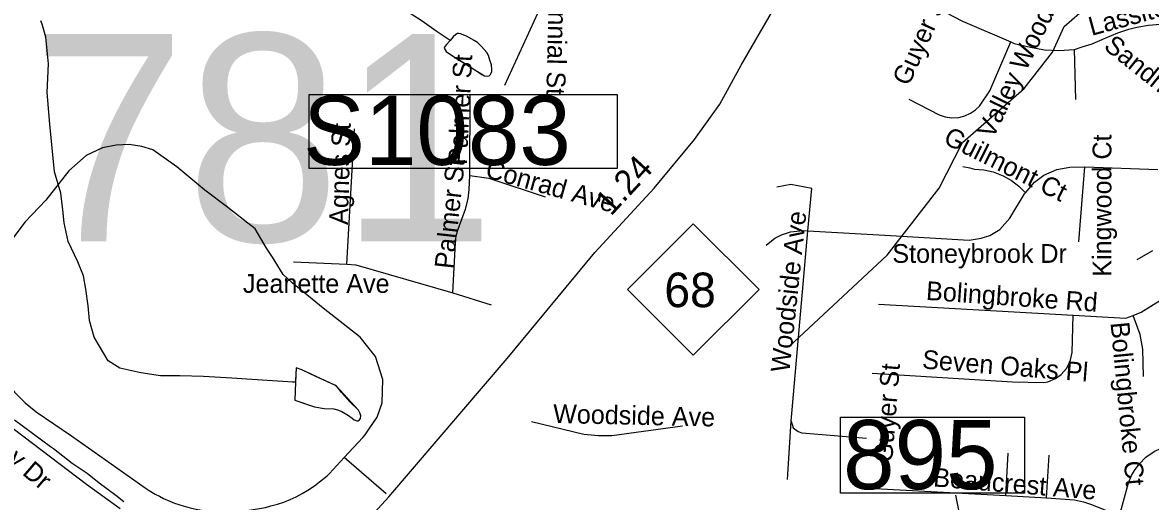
# Model space of a CAD drawing. Extents: x 1662474 to 1856135, y 779280 to 917889.
# Drawn here: x 1701527 to 1707230, y 816221 to 818646 of the extents above; entities that cross this region are included whole.
import ezdxf

# ---------------------------------------------------------------- set-up
doc = ezdxf.new("R2010")
doc.units = 0
for name, color, linetype in [('Exist Hydrographic Misc Water Feature', 7, 'Continuous'), ('Exist Hydrographic River Shore Label', 7, 'Continuous'), ('Exist Road Non-System Structure Non-Sys Other Number Label', 7, 'Continuous'), ('Exist Road Non-System Type 51', 7, 'Continuous'), ('Exist Road Non-System Type 51 Label', 7, 'Continuous'), ('Exist Road Primary NC Service Mileage Hundredths English Label', 7, 'Continuous'), ('Exist Road Primary NC Shield CELL', 7, 'Continuous'), ('Exist Road Primary NC Shield Number Label', 7, 'Continuous'), ('Exist Road Primary NC UnDivided 4 Lane Attributed', 7, 'Continuous'), ('Exist Road Secondary Structure Standard Bridge Number Label', 7, 'Continuous'), ('Exist Road Secondary Type 51 Divided Attributed', 7, 'Continuous'), ('Exist Road Secondary Type 51 Label', 7, 'Continuous')]:
    doc.layers.add(name, color=color, linetype=linetype)

msp = doc.modelspace()

# ---------------------------------------------------------------- linework, layer by layer
at = {"layer": 'Exist Hydrographic Misc Water Feature'}
for points in [[(1705403.1, 817006.2), (1705899.1, 817468.7), (1706161.1, 817808), (1706280.1, 818038.8), (1706591.2, 818311.4), (1706734.1, 818495.6), (1706794.2, 818625.6), (1706870.2, 818693.1), (1707195.2, 818755.4), (1707354.2, 818847.4), (1707919.2, 819433.2), (1708288.2, 819714.6), (1708465.1, 819960.4), (1708625.2, 820118.1), (1708860.2, 820274.1), (1709089.8, 820345.3), (1709286.2, 820386.9)], [(1703688.7, 818555.9), (1703618.8, 818602.5), (1703547.1, 818653.2), (1703369.5, 818770), (1703281.5, 818802.2), (1703191.3, 818796.6), (1703111.4, 818790.9), (1703005.5, 818787.2), (1702903.3, 818807.4), (1702805.7, 818855.3), (1702721.9, 818903.8), (1702520.3, 819026.9), (1702458.5, 819065.1), (1702382, 819126.5)], [(1702907.3, 816825.5), (1702891.5, 816825.8), (1702843.5, 816828.5), (1702763.6, 816834.2), (1702585.4, 816845.2), (1702441.6, 816853.9), (1702321.4, 816857.9), (1702223.6, 816856.7), (1702125.7, 816872.6), (1702019.6, 816895.3), (1701959.7, 816933.4), (1701888.3, 817053.9), (1701864.8, 817137.2), (1701858.9, 817212), (1701847.3, 817295.9), (1701835.5, 817363.5), (1701805.8, 817433.8), (1701758.3, 817538.2), (1701736.6, 817632.2), (1701730.6, 817697.9), (1701721.2, 817781.8), (1701687.7, 817890), (1701664.4, 818131.8), (1701651.1, 818292), (1701657.6, 818436.3), (1701644.3, 818572), (1701626.6, 818638), (1701618.8, 818654.6)], [(1703688.7, 818555.9), (1703670.6, 818534.9), (1703662.4, 818524.4), (1703658.6, 818516.3), (1703668.5, 818498.9), (1703710.3, 818470.1), (1703752.2, 818444.7), (1703818.1, 818403.9), (1703849.9, 818383.6), (1703862, 818375.9), (1703876, 818374), (1703886.1, 818375.5), (1703893.3, 818382.7), (1703896.8, 818389.2), (1703900, 818397.4), (1703900.2, 818408), (1703897.1, 818431.9), (1703890.2, 818455.8), (1703882.4, 818478.9), (1703874.4, 818493.8), (1703846.6, 818525.6), (1703826.7, 818544.9), (1703810.6, 818555.9), (1703770.7, 818576.4), (1703740.5, 818588.5), (1703733.5, 818590.3), (1703726.7, 818590.4), (1703717, 818584.8), (1703704.6, 818574.4), (1703688.7, 818555.9)], [(1703688.7, 818555.9), (1703670.6, 818534.9), (1703662.4, 818524.4), (1703658.6, 818516.3), (1703668.5, 818498.9), (1703710.3, 818470.1), (1703862, 818375.9), (1703876, 818374), (1703886.1, 818375.5), (1703893.3, 818382.7), (1703896.8, 818389.2), (1703900, 818397.4), (1703900.2, 818408), (1703897.1, 818431.9), (1703890.2, 818455.8), (1703882.4, 818478.9), (1703874.4, 818493.8), (1703846.6, 818525.6), (1703826.7, 818544.9), (1703810.6, 818555.9), (1703770.7, 818576.4), (1703740.5, 818588.5), (1703733.5, 818590.3), (1703726.7, 818590.4), (1703717, 818584.8), (1703704.6, 818574.4), (1703688.7, 818555.9)], [(1707239.3, 817489.9), (1707160.9, 817444.6)], [(1702907.3, 816825.5), (1702903.2, 816733.7), (1702953.1, 816717.9), (1703003.1, 816699.7), (1703051.1, 816691.3), (1703101.1, 816689.5), (1703118.9, 816685.8), (1703141.1, 816677.2), (1703174.9, 816656.8), (1703193, 816642.5), (1703204.4, 816634), (1703217, 816628.8), (1703224.2, 816629.6), (1703228.9, 816632.7), (1703235.3, 816640.8), (1703237, 816654.7), (1703232.7, 816670.4), (1703225, 816682.9), (1703181.4, 816726.4), (1703139.5, 816773.1), (1703125.6, 816790.7), (1703113.6, 816804.9), (1703105.7, 816810.8), (1703009.7, 816853.8), (1702977.9, 816869.2), (1702939.8, 816888), (1702909.8, 816897.7), (1702907.7, 816833.7), (1702907.3, 816825.5)], [(1702907.3, 816825.5), (1702903.2, 816733.7), (1703003.1, 816699.7), (1703051.1, 816691.3), (1703101.1, 816689.5), (1703118.9, 816685.8), (1703141.1, 816677.2), (1703174.9, 816656.8), (1703193, 816642.5), (1703204.4, 816634), (1703217, 816628.8), (1703224.2, 816629.6), (1703228.9, 816632.7), (1703235.3, 816640.8), (1703237, 816654.7), (1703232.7, 816670.4), (1703225, 816682.9), (1703113.6, 816804.9), (1703105.7, 816810.8), (1702939.8, 816888), (1702909.8, 816897.7), (1702907.3, 816825.5)]]:
    msp.add_lwpolyline(points, dxfattribs=at)
at = {"layer": 'Exist Hydrographic River Shore Label'}
msp.add_line((1705599.6, 821891.5), (1703963.2, 818327.1), dxfattribs=at)
msp.add_lwpolyline([(1702976.4, 818281.8), (1704533.1, 818281.8), (1704533.1, 817907.3), (1702976.4, 817907.3)], close=True, dxfattribs=at)
at = {"layer": 'Exist Road Non-System Type 51'}
for p, q in [((1706852.4, 818256.2), (1706844.8, 818510.1)), ((1703788.6, 817871.5), (1703790.6, 818278.4)), ((1703166.9, 817423.2), (1703205.4, 818108.5)), ((1706867.9, 817535.4), (1706897.2, 817915.6)), ((1706897.2, 817915.6), (1707266.5, 817902.8)), ((1705413, 816628), (1705497.2, 817591.5)), ((1705497.2, 817591.5), (1705887.2, 817568.7)), ((1702897.2, 817434), (1703166.9, 817423.2)), ((1703702, 817276.8), (1703895.9, 817216.9)), ((1705854.4, 817220.4), (1706839.5, 817163.9)), ((1705393.9, 816332.4), (1705413, 816628)), ((1706498.9, 816250.9), (1706510.6, 816465.5)), ((1706704.6, 816239.5), (1706717.1, 816455.2)), ((1703365.5, 816259.2), (1703153.8, 816443.2)), ((1705773.4, 816290.2), (1706498.9, 816250.9)), ((1706498.9, 816250.9), (1706704.6, 816239.5))]:
    msp.add_line(p, q, dxfattribs=at)
for points in [[(1706195.6, 818697.5), (1706279.9, 818653.4), (1706524.2, 818547.9)], [(1706844.8, 818510.1), (1706885.1, 818523.2), (1706934.5, 818538.7), (1707001.1, 818566.8), (1707064.6, 818593.2), (1707119.8, 818612.8), (1707161.2, 818623.2), (1707219.8, 818633.4), (1707278.1, 818637.7), (1707347.9, 818634.5), (1707410.4, 818621.1), (1707469.6, 818611.7), (1707521.6, 818609.4), (1707642.9, 818627.4)], [(1706007.5, 818258.9), (1706161.8, 818178.1), (1706191.8, 818168.4), (1706222.9, 818163.9), (1706260.5, 818165.8), (1706290.9, 818173.6), (1706319.5, 818186.5), (1706345.8, 818204.1), (1706366, 818223.5), (1706417.6, 818300.7), (1706524.2, 818547.9)], [(1706524.2, 818547.9), (1706541.4, 818540.5), (1706622.4, 818520.9), (1706694.1, 818508.5), (1706767.2, 818504.9), (1706844.8, 818510.1)], [(1703153.8, 816443.2), (1703247.1, 816545.4), (1703258.6, 816559.2), (1703269.4, 816573.7), (1703279.6, 816588.9), (1703319.1, 816647.2), (1703345.1, 816720.9), (1703349.2, 816838.2), (1703312.2, 816954.5), (1703234.6, 817052.9), (1703047.4, 817199.1), (1702890.1, 817328.5), (1702843.8, 817369.9), (1702790.8, 817458.9), (1702760.6, 817503.6), (1702702.2, 817602), (1702666.4, 817630.6), (1702565, 817710.4), (1702448.2, 817798), (1702306.2, 817915.9), (1702185, 818001.4), (1702130.1, 818018.5), (1702065.6, 818028.8), (1701999.6, 818025.6), (1701930.4, 818011.4), (1701848.8, 817972.4), (1701760.4, 817894.9), (1701645.1, 817747.1), (1701540.6, 817636.9), (1701427.2, 817486.8)], [(1703702, 817276.8), (1703715.1, 817531.7), (1703719.9, 817568.4), (1703729.2, 817600.7), (1703765.8, 817700.7), (1703779.9, 817753.9), (1703785.8, 817801.4), (1703788.6, 817871.5)], [(1703788.6, 817871.5), (1703883.9, 817857.6), (1704168.9, 817764.2)], [(1706281.8, 817918), (1706316.6, 817909.9), (1706340.5, 817903), (1706388, 817899.6), (1706434.5, 817889.4), (1706484.9, 817870.2), (1706526.4, 817846.9), (1706564.6, 817818), (1706598, 817784.1)], [(1706598, 817784.1), (1706643.9, 817837.7), (1706690.6, 817873.1), (1706756.2, 817901.4), (1706821.9, 817913.8), (1706897.2, 817915.6)], [(1705497.2, 817591.5), (1705517.1, 817806.4), (1705411.9, 817826.4), (1705340.9, 817812.8)], [(1705887.2, 817568.7), (1706312.6, 817543.4), (1706373.1, 817554.5), (1706416.9, 817567.9), (1706468.9, 817598.4), (1706518.2, 817655.8), (1706592.8, 817779.2), (1706598, 817784.1)], [(1705285.9, 817518.8), (1705330.6, 817554.5), (1705363.6, 817571), (1705410.4, 817587.2), (1705473.6, 817592.8), (1705497.2, 817591.5)], [(1703166.9, 817423.2), (1703212.8, 817420.1), (1703702, 817276.8)], [(1707141.6, 817162.9), (1707182.2, 817178.9), (1707377.5, 817301.4)], [(1705822.1, 816870), (1706532.1, 816827.7), (1706688.9, 816822.8), (1706711.6, 816827.2), (1706749.1, 816843.2), (1706777.8, 816863.7), (1706804.9, 816894.4), (1706823.8, 816930.6), (1706833.6, 816976.2), (1706839.5, 817163.9)], [(1706839.5, 817163.9), (1707105.4, 817148.7), (1707141.6, 817162.9)], [(1707193.9, 816853.7), (1707190.4, 816992.9), (1707176.8, 817066.2), (1707141.6, 817162.9)], [(1701353.2, 817101.4), (1701358.8, 817051.4), (1701367.9, 817006.4), (1701378.1, 816968.9), (1701392.9, 816923.2), (1701404.4, 816897), (1701432.5, 816846.1), (1701452.1, 816817.8), (1701466.9, 816799.1), (1701485.5, 816775.2), (1701539.6, 816720.1), (1701596, 816675.2), (1701773.6, 816553.2), (1702147.4, 816290.2), (1702167.4, 816276.9), (1702197.9, 816258.7), (1702218.6, 816247.4), (1702239.6, 816236.4), (1702272.4, 816222.5), (1702294.4, 816213.2), (1702316.4, 816205.4), (1702339.4, 816198.4), (1702373.9, 816189.4), (1702397, 816183.9)], [(1704099.6, 816626.2), (1704365.2, 816561.6), (1704438.1, 816555.2), (1704505.6, 816554.5), (1704863.6, 816603.4)], [(1705413, 816628), (1705423, 816594.7), (1705448.4, 816575.8), (1705467.1, 816568.4), (1705794.6, 816542.4)], [(1707073.4, 816147.9), (1707119.2, 816315.7), (1707133.9, 816352.7), (1707148.6, 816378.4), (1707172.2, 816410.4), (1707207.1, 816445.4), (1707247.6, 816473.7), (1707283.2, 816491), (1707340.5, 816507.5), (1707399.9, 816511.2), (1707439.4, 816506.8), (1707680.4, 816464.5), (1707814, 816462.6), (1707873.9, 816466.9), (1707962.6, 816484.9), (1708047.1, 816516.7), (1708065.9, 816526.2), (1708144.9, 816595.4)], [(1702397, 816183.9), (1702431.9, 816177.9), (1702467.4, 816173.4), (1702499.6, 816170.8), (1702531.6, 816169.4), (1702564.2, 816169.2), (1702596.5, 816170.2), (1702628.8, 816172.6), (1702661.1, 816175.5), (1702692.9, 816179.9), (1702724.6, 816185.5), (1702756.1, 816191.5), (1702782.9, 816198.4), (1702815.6, 816207.2), (1702847.9, 816218.2), (1702879.4, 816230.9), (1702910.4, 816245.4), (1702940.4, 816261.1), (1702969.8, 816278.7), (1703002.2, 816300.4), (1703028.5, 816320.4), (1703066.6, 816351.1), (1703079.1, 816362.1), (1703153.8, 816443.2)], [(1706704.6, 816239.5), (1706846.4, 816229.6), (1706891.4, 816218.9), (1706931.4, 816205.7), (1707073.4, 816147.9)]]:
    msp.add_lwpolyline(points, dxfattribs=at)
at = {"layer": 'Exist Road Primary NC Shield CELL'}
msp.add_lwpolyline([(1704584.8, 817294.7), (1704917.8, 817627.7), (1705250.8, 817294.7), (1704917.8, 816961.7)], close=True, dxfattribs=at)
at = {"layer": 'Exist Road Primary NC UnDivided 4 Lane Attributed'}
msp.add_lwpolyline([(1702688.7, 815483), (1702915.7, 815734.2), (1703001.2, 815831.8), (1703379.3, 816244.8), (1703977.1, 816944.7), (1704421.2, 817482.5), (1704720.1, 817806.8), (1704925, 818054.4), (1705053.1, 818233.6), (1705159.8, 818430.8), (1705375.3, 818805.7), (1705656.2, 819331), (1705867.2, 819708.4), (1706138.6, 820186.4), (1706455.9, 820774.6)], dxfattribs=at)
at = {"layer": 'Exist Road Secondary Structure Standard Bridge Number Label'}
msp.add_line((1706868.7, 813137.3), (1706245.4, 816253.8), dxfattribs=at)
msp.add_lwpolyline([(1705663, 816648), (1706592, 816648), (1706592, 816263.9), (1705663, 816263.9)], close=True, dxfattribs=at)
at = {"layer": 'Exist Road Secondary Type 51 Divided Attributed'}
for points in [[(1702021.2, 816183.2), (1701850.9, 816307), (1701392.8, 816652.3), (1701315.1, 816721.4), (1701215.9, 816841.5), (1701145.4, 816951.2), (1700892.9, 817376.1), (1700837, 817440.4), (1700801.1, 817471.7), (1700721.2, 817535.4), (1700594.4, 817616.9), (1700369.4, 817767.8), (1700293.6, 817819.7), (1700213.2, 817865.4), (1700053.9, 817948.5), (1699914.1, 818020.8), (1699722.8, 818106.6), (1699637.2, 818136.8), (1699451.1, 818197.1), (1699283.5, 818242.4), (1699113.4, 818276.9), (1699004.7, 818288.4), (1698858.8, 818300.2), (1698384.4, 818326.3)], [(1701485.5, 816635), (1701577.7, 816566.7), (1701668.1, 816499.4), (1701684.1, 816488.8), (1701778.5, 816415.7), (1701853, 816364.3), (1701915, 816315.7), (1701998.4, 816253.4), (1702039.7, 816220.8)]]:
    msp.add_lwpolyline(points, dxfattribs=at)

# ---------------------------------------------------------------- texts
at = {"layer": 'Exist Hydrographic River Shore Label'}
msp.add_text('S1083', height=350, dxfattribs=at).set_placement((1702945.7, 817925.2))
at = {"layer": 'Exist Road Non-System Structure Non-Sys Other Number Label'}
msp.add_text('J781', height=1049.86, dxfattribs=at).set_placement((1700870.1, 817538.4))
at = {"layer": 'Exist Road Non-System Type 51 Label'}
for s, rotation, p in [('N Centennial St', 268.5706, (1704197.4, 819169.2)), ('Valley Wood Pl', 64.019, (1706433.2, 818053.4)), ('Guyer St', 65.6266, (1706007.4, 818320.5)), ('Lassiter Dr', 15.2557, (1706931.8, 818578.1)), ('Sandhurst Ct', 321.3243, (1706988.5, 818516.4)), ('Palmer St', 87.1524, (1703773.2, 817924.3)), ('Agnes St', 88.4261, (1703172.1, 817620.7)), ('Guilmont Ct', 333.422, (1706176.8, 818037.1)), ('Kingwood Ct', 90, (1707032.2, 817359.2)), ('Palmer St', 83.7745, (1703704, 817395.8)), ('Conrad Ave', 344.3493, (1703861.3, 817864.1)), ('Woodside Ave', 83.9406, (1705403.9, 816871.7)), ('Bolingbroke Rd', 356.0105, (1706092.9, 817242.1)), ('Bolingbroke Ct', 275.4373, (1707027.5, 817126.1)), ('Seven Oaks Pl', 355.4464, (1706073, 816894.5)), ('Guyer St', 85.4545, (1705923.6, 816416.1)), ('Woodside Ave', 358.7398, (1704208.6, 816618.7)), ('Beaucrest Ave', 355.3114, (1706129.1, 816297.6))]:
    msp.add_text(s, height=95, rotation=rotation, dxfattribs=at).set_placement(p)
for s, p in [('Stoneybrook Dr', (1705924.6, 817429.3)), ('Jeanette Ave', (1702641.1, 817277.2))]:
    msp.add_text(s, height=95, dxfattribs=at).set_placement(p)
at = {"layer": 'Exist Road Primary NC Service Mileage Hundredths English Label'}
msp.add_text('1.24', height=125, rotation=47.3389, dxfattribs=at).set_placement((1704501.5, 817661.9))
at = {"layer": 'Exist Road Primary NC Shield Number Label'}
msp.add_text('68', height=175, dxfattribs=at).set_placement((1704771.9, 817204.9))
at = {"layer": 'Exist Road Secondary Structure Standard Bridge Number Label'}
msp.add_text('895', height=350, dxfattribs=at).set_placement((1705675.5, 816283.6))
at = {"layer": 'Exist Road Secondary Type 51 Label'}
msp.add_text('E Hartley Dr', height=95, rotation=319.301, dxfattribs=at).set_placement((1701098.2, 816724.8))

doc.saveas('drawing.dxf')
